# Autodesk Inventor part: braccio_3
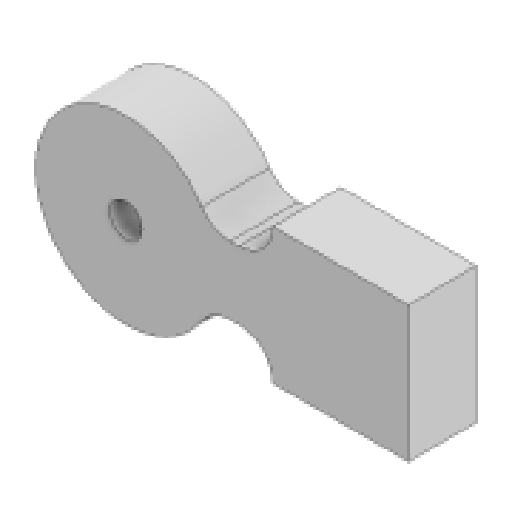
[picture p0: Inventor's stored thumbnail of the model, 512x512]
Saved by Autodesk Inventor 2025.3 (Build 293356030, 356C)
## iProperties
Created: 2026-03
Part Number: braccio_3
Material: Generico
Document SubType Name: Modeling
Designer: Ryzen5700u
Density: 1 g/cm^3
Appearance: Default
Author: Ryzen5700u
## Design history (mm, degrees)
sketch "Schizzo1"
  geometry: L1 (-25, 6)-(0, 6); L2 (0, 6)-(0, -6); L3 (0, -6)-(-25, -6); L4 (-25, -6)-(-25, 6); L5 (0, 0)-(13.023, 0); L6 (0, 6)-(-12, 6); L7 (-12, 6)-(-12, -6); L8 (-12, -6)-(0, -6); L9 (0, -6)-(0, 6); L10 (-17.584, 3)-(-12, 3); L11 (-17.584, -3)-(-12, -3); A1 r 8 centre (-25, 0) between (-17.584, 3) and (-17.584, -3); 4 further points
  constraints: 22 end point, 4 horizontal, 4 parallel, 3 perpendicular, 3 point on line, 2 midpoint, 2 point on circle, 1 centre point, 1 coincident, 1 other
  dimensions: "d3" = 25 distance of L1.start L1.end; "d4" = 16 diameter of A1; "d16" = 12 distance between parallel lines of L3 L1; "d17" = 12 distance of L8.end L7.end; "d18" = 3 distance from line of A1.centre L10; "d19" = 3 distance from line of A1.centre L11
extrude "Estrusione1" new body sketch "Schizzo1" distance "d1" = 6; taper "d2" = 0 deg
sketch "Schizzo3"
  geometry: A1 r 8 centre (25, 0) between (17.584, -3) and (17.584, 3) reference; 4 further points
  constraints: 1 coincident
hole "Foro1" sketch "Schizzo3" at (25, 0) diameter "d9" = 2.9; stored, may be unused: countersink angle "d13" = 82 deg, drill point angle "d15" = 118 deg; dims "d10" = 6, "d11" = 4.5, "d12" = 2, "d14" = 8
fillet "Raccordo2" dims "d20" = 3
node "Solido1"
